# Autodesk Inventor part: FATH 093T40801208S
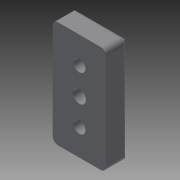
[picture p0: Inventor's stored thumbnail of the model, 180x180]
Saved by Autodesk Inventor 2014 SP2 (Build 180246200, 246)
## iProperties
Created: 2018-10
Part Number: FATH 093T40801208S
Material: Generic
Catalog Web Link: www.cadenas.de
Description: Transport and Base Plate 40 x 80-Die-cast Zinc
Vendor: FATH
Document SubType Name: Modeling
Designer: psadmin
Manufacturer: FATH
Mass: 45.2462 g
Surface Area: 111.419 cm^2
Volume: 45.2462 cm^3
Density: 1 g/cm^3
Appearance: PSOLRGB-175-175-175
Category: PARTsolutions
Company: FATH
Title: FATH 093T40801208S
Author: Cadenas PARTsolutions
Comments: Die-cast Zinc
PSOL_IDENT_0: {$CADENAS_DATA\23d-libs\fath\zubehoer_alu_sys\fussplatten\093t4080.prj},194 {VTYP=3D},{NB=FATH 093T4
PSOL_IDENT_1: 0801208S},{LINA=FATH 093T40801208S},{NN=Transport and Base Plate 40 x 80},{DATE=19.02.2018 15:31:06}
PSOL_IDENT_2: ,{GEOMDATE=26.05.2005},{VERSION=},{LINEID=750},{WBVAR=},{WBNUMERIC=}  {NB=FATH 093T40801208S},{LINA=
PSOL_IDENT_3: FATH 093T40801208S},{KT=DUMMY},{BO=für M8},{D=9.0},{DIM=80x40},{A=40},{M=M12},{O=pulverbeschichtet},
PSOL_IDENT_4: {ARTNR=093T40801208S},{PRTNO=},{L=80},{B=40},{H=16},{D1=9.0},{D2=15},{T=9.0},{GEW=12},{KD=9.9},{R1=4
PSOL_IDENT_5: .0},{R2=3},{FO=1}
NN: Transport- und Fußplatte 40x80
NT: Zinkdruckguss
NB: FATH 093T40801208S
NBSYN: FATH $ARTNR.
LINA: FATH 093T40801208S
BO: für M8
D: 9
DIM: 80x40
A: 40
M: M12
O: pulverbeschichtet
ARTNR: 093T40801208S
SUPPLIER: FATH
ARTICLENO: FATH 093T40801208S
BOMINFO: FATH 093T40801208S
CREATOR: CADENAS GmbH
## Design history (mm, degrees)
sketch "Skizze_1"
  geometry: L1 (16, 40)-(-16, 40); L2 (-20, 36)-(-20, -36); L3 (-16, -40)-(16, -40); L4 (20, -36)-(20, 36); A1 r 4 centre (16, 36) between (20, 36) and (16, 40); A2 r 4 centre (-16, 36) between (-16, 40) and (-20, 36); A3 r 4 centre (-16, -36) between (-20, -36) and (-16, -40); A4 r 4 centre (16, -36) between (16, -40) and (20, -36)
  constraints: 8 end point, 8 point on circle, 4 centre point
extrude "Extrusion1" join sketch "Skizze_1" distance "d0" = 16; taper "d1" = 0 deg
sketch "Skizze_2"
  geometry: L1 (19, 43)-(0, 43); L2 (0, 43)-(0, 40); L3 (0, 40)-(13, 40); L4 (16, 37)-(16, -37); L5 (13, -40)-(0, -40); L6 (0, -40)-(0, -43); L7 (0, -43)-(19, -43); L8 (19, -43)-(19, 43); A1 r 3 centre (13, 37) between (16, 37) and (13, 40); A2 r 3 centre (13, -37) between (13, -40) and (16, -37)
  constraints: 16 end point, 4 point on circle, 2 centre point
extrude "Extrusion2" cut sketch "Skizze_2" stored distance "d2" = 40; taper "d3" = 0 deg
sketch "Skizze_3"
  geometry: L1 (-23, 19)-(-23, 0); L2 (-23, 0)-(-20, 0); L3 (-20, 0)-(-20, 13); L4 (-17, 16)-(17, 16); L5 (20, 13)-(20, 0); L6 (20, 0)-(23, 0); L7 (23, 0)-(23, 19); L8 (23, 19)-(-23, 19); A1 r 3 centre (-17, 13) between (-17, 16) and (-20, 13); A2 r 3 centre (17, 13) between (20, 13) and (17, 16)
  constraints: 16 end point, 4 point on circle, 2 centre point
extrude "Extrusion3" cut sketch "Skizze_3" stored distance "d4" = 80; taper "d5" = 0 deg
sketch "Skizze_4"
  geometry: L1 (18, 20)-(0, 20); L2 (0, 20)-(0, 24.5); L3 (0, 24.5)-(7, 24.5); L4 (7, 24.5)-(7, 27.5); L5 (7, 27.5)-(18, 27.5); L6 (18, 27.5)-(18, 20); L7 (18, 20)-(0, 20)
  constraints: 14 end point
revolve "Revolution1" sketch "Skizze_4" stored, may be unused: angle "d6" = 360 deg
sketch "Skizze_5"
  geometry: L1 (18, -20)-(0, -20); L2 (0, -20)-(0, -15.5); L3 (0, -15.5)-(7, -15.5); L4 (7, -15.5)-(7, -12.5); L5 (7, -12.5)-(18, -12.5); L6 (18, -12.5)-(18, -20); L7 (18, -20)-(0, -20)
  constraints: 14 end point
revolve "Revolution2" sketch "Skizze_5" stored, may be unused: angle "d7" = 360 deg
sketch "Skizze_6"
  geometry: L1 (16, 0)-(0, 0); L2 (0, 0)-(0, 4.95); L3 (0, 4.95)-(16, 4.95); L4 (16, 4.95)-(16, 0); L5 (16, 0)-(0, 0)
  constraints: 10 end point
revolve "Revolution3" sketch "Skizze_6" stored, may be unused: angle "d8" = 360 deg
body "Solid1"
